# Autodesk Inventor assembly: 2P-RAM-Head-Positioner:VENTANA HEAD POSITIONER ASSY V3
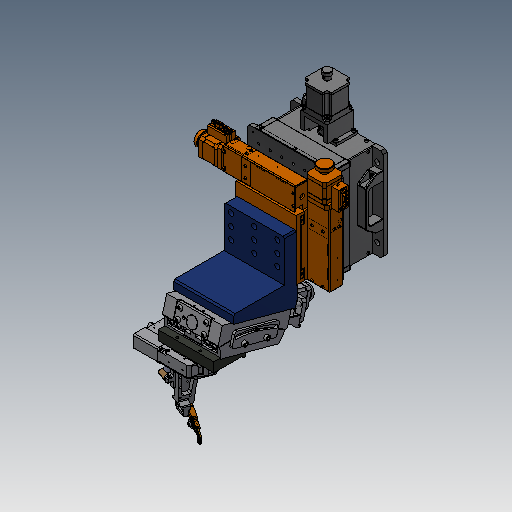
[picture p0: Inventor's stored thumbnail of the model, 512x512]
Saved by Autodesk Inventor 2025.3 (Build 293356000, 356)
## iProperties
RuleStatus: InUse
Created: 2022-09
Catalog Web Link: https://www.janelia.org/
Vendor: HHMI: JRC - jET
Document SubType Name: Assembly
Designer: sohna
AfterDocSave0: file://Part Number Cleaner
DESIGN DEPARTMENT: HHMI: JRC - jET
LAB/DEPT: A. LEE (LAB)
ALTERED ITEM PART NUMBER: N/A
ALTERED ITEM VENDOR: N/A
ALTERED ITEM DESCRIPTION: N/A
PART NUMBER - LEGACY: Standard
Author: sohna
Revision Number: 0
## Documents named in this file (17)
- C:\_WORKSPACE\DATA\PROJECTS\_PROJECTS BY LAB\PACHITARIU (LAB)\VENTANA SCOPE\VENTANA HEAD POSITIONER ASSY V3.iam
- C:\_WORKSPACE\DATA\PROJECTS\_PROJECTS BY LAB\SVOBODA (LAB)\MOUSE POSITIONING SYSTEMS\MCAD\BALL SETUP\MBS INNER POSARM.ipt
- C:\_WORKSPACE\DATA\PROJECTS\_PROJECTS BY LAB\SVOBODA (LAB)\MOUSE POSITIONING SYSTEMS\MCAD\BALL SETUP\MBS Inline Tab Asm.iam
- C:\_WORKSPACE\DATA\COMMON\Zaber\X-RSW60.ipt
- C:\_WORKSPACE\DATA\COMMON\Optics Focus\OPTICS FOCUS_MOG-130-10.ipt
- C:\_WORKSPACE\DATA\PROJECTS\_PROJECTS BY LAB\PACHITARIU (LAB)\BERGAMO TREADMILL SETUP\TLB GONIOMETER SHIELD.ipt
- C:\_WORKSPACE\DATA\COMMON\Optics Focus\OPTICS FOCUS MOZ-200-25.iam
- C:\_WORKSPACE\DATA\COMMON\Optics Focus\OPTICS FOCUS_MOXY-01-50-50.ipt
- C:\_WORKSPACE\DATA\PROJECTS\_PROJECTS BY LAB\PACHITARIU (LAB)\VENTANA SCOPE\VEN_MOD_THORLABS_MB2020_M - Aluminium Breadboard 200 x 200mm.ipt
- C:\_WORKSPACE\DATA\PROJECTS\_PROJECTS BY LAB\PACHITARIU (LAB)\VENTANA SCOPE\VEN ROT TO GONIO BRKT.ipt
- C:\_WORKSPACE\DATA\PROJECTS\_PROJECTS BY LAB\PACHITARIU (LAB)\VENTANA SCOPE\VEN GONIO TO XY BRKT V2.ipt
- C:\_WORKSPACE\DATA\COMMON\McMaster\MCMASTER_91292A441_18-8 Stainless Steel Socket Head Screw.ipt
- C:\_WORKSPACE\DATA\COMMON\Optics Focus\OPTICS FOCUS_25MP.ipt
- C:\_WORKSPACE\DATA\PROJECTS\_PROJECTS BY LAB\SVOBODA (LAB)\MOUSE POSITIONING SYSTEMS\MCAD\BALL SETUP\CE-075-12C.ipt
- C:\_WORKSPACE\DATA\PROJECTS\_PROJECTS BY LAB\PACHITARIU (LAB)\VENTANA SCOPE\VEN_MAG_LOCK_BRKT.ipt
- C:\_WORKSPACE\DATA\PROJECTS\_PROJECTS BY LAB\PACHITARIU (LAB)\VENTANA SCOPE\VEN MAG PLATE BRKT.ipt
- C:\_WORKSPACE\DATA\PROJECTS\_PROJECTS BY LAB\PACHITARIU (LAB)\VENTANA SCOPE\APW_EML20MM-12.ipt
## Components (18 placed, 16 different names)
1. MBS INNER POSARM:1
2. MBS Inline Tab Asm:1 [sub-assembly] — Mate:1, Mate:2, Flush:1, Mate:50
3. X-RSW60:1 — Mate:51, Mate:52, Mate:53, Angle:9
4. OPTICS FOCUS_MOG-130-10:2
5. TLB GONIOMETER SHIELD:1 — Mate:35, Mate:36, Tangent:1
6. OPTICS FOCUS MOZ-200-25:1 [sub-assembly] — Angle:5, Insert:5, Angle:8, Mate:55, Flush:5, Angle:11, Insert:10
7. OPTICS FOCUS_MOXY-01-50-50:1 — Angle:5, Mate:56, Mate:61, Mate:62, Insert:11
8. VEN_MOD_THORLABS_MB2020_M - Aluminium Breadboard 200 x 200mm:1 — Insert:5, Angle:8
9. VEN ROT TO GONIO BRKT:1 — Flush:4, Mate:59, Mate:60, Insert:7, Insert:8, Insert:9
10. VEN GONIO TO XY BRKT V2:1 — Flush:6, Mate:61, Mate:62
11. MCMASTER_91292A441_18-8 Stainless Steel Socket Head Screw:1 — Insert:7
12. MCMASTER_91292A441_18-8 Stainless Steel Socket Head Screw:2 — Insert:8
13. MCMASTER_91292A441_18-8 Stainless Steel Socket Head Screw:3 — Insert:9
14. OPTICS FOCUS_25MP:1 — Angle:11, Insert:10, Insert:11
15. CE-075-12C:1 — Mate:63, Mate:64
16. VEN_MAG_LOCK_BRKT:1 — Angle:12, Insert:12, Mate:63, Mate:64, Insert:13
17. VEN MAG PLATE BRKT:1 — Mate:65, Mate:66, Mate:67
18. APW_EML20MM-12:1 — Insert:13
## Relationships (37: Mate 19, Insert 8, Angle 5, Flush 4, Tangent 1)
- Mate:1: MBS Inline Tab Asm:1
- Mate:2: MBS Inline Tab Asm:1
- Flush:1: MBS Inline Tab Asm:1
- Mate:35: TLB GONIOMETER SHIELD:1
- Mate:36: TLB GONIOMETER SHIELD:1
- Tangent:1: TLB GONIOMETER SHIELD:1
- Angle:5: OPTICS FOCUS MOZ-200-25:1 ↔ OPTICS FOCUS_MOXY-01-50-50:1
- Insert:5: OPTICS FOCUS MOZ-200-25:1 ↔ VEN_MOD_THORLABS_MB2020_M - Aluminium Breadboard 200 x 200mm:1
- Angle:8: OPTICS FOCUS MOZ-200-25:1 ↔ VEN_MOD_THORLABS_MB2020_M - Aluminium Breadboard 200 x 200mm:1
- Mate:50: MBS Inline Tab Asm:1
- Mate:51: X-RSW60:1
- Mate:52: X-RSW60:1
- Mate:53: X-RSW60:1
- Angle:9: X-RSW60:1
- Mate:55: OPTICS FOCUS MOZ-200-25:1
- Mate:56: OPTICS FOCUS_MOXY-01-50-50:1
- Flush:4: VEN ROT TO GONIO BRKT:1
- Mate:59: VEN ROT TO GONIO BRKT:1
- Mate:60: VEN ROT TO GONIO BRKT:1
- Flush:5: OPTICS FOCUS MOZ-200-25:1
- Flush:6: VEN GONIO TO XY BRKT V2:1
- Mate:61: OPTICS FOCUS_MOXY-01-50-50:1 ↔ VEN GONIO TO XY BRKT V2:1
- Mate:62: OPTICS FOCUS_MOXY-01-50-50:1 ↔ VEN GONIO TO XY BRKT V2:1
- Insert:7: VEN ROT TO GONIO BRKT:1 ↔ MCMASTER_91292A441_18-8 Stainless Steel Socket Head Screw:1
- Insert:8: VEN ROT TO GONIO BRKT:1 ↔ MCMASTER_91292A441_18-8 Stainless Steel Socket Head Screw:2
- Insert:9: VEN ROT TO GONIO BRKT:1 ↔ MCMASTER_91292A441_18-8 Stainless Steel Socket Head Screw:3
- Angle:11: OPTICS FOCUS MOZ-200-25:1 ↔ OPTICS FOCUS_25MP:1
- Insert:10: OPTICS FOCUS MOZ-200-25:1 ↔ OPTICS FOCUS_25MP:1
- Insert:11: OPTICS FOCUS_MOXY-01-50-50:1 ↔ OPTICS FOCUS_25MP:1
- Angle:12: VEN_MAG_LOCK_BRKT:1
- Insert:12: VEN_MAG_LOCK_BRKT:1
- Mate:63: CE-075-12C:1 ↔ VEN_MAG_LOCK_BRKT:1
- Mate:64: CE-075-12C:1 ↔ VEN_MAG_LOCK_BRKT:1
- Mate:65: VEN MAG PLATE BRKT:1
- Mate:66: VEN MAG PLATE BRKT:1
- Mate:67: VEN MAG PLATE BRKT:1
- Insert:13: VEN_MAG_LOCK_BRKT:1 ↔ APW_EML20MM-12:1
